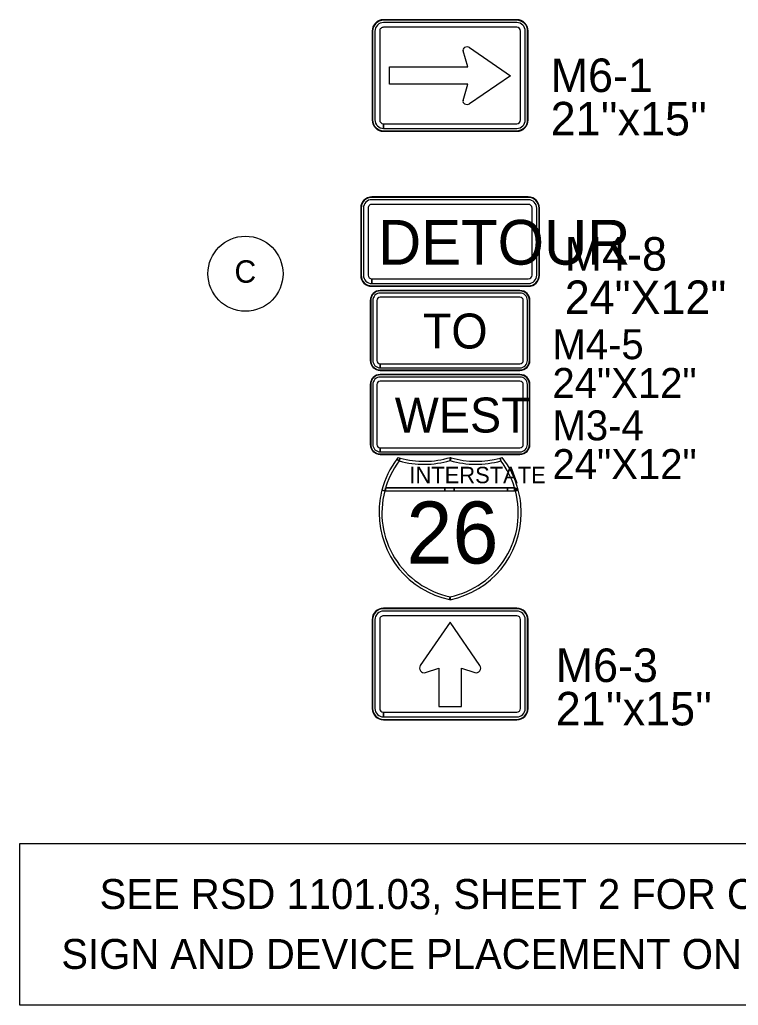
# Model space of a CAD drawing. Extents: x 886234 to 968767, y 455416 to 684046.
# Drawn here: x 931806 to 935407, y 525352 to 530289 of the extents above; entities that cross this region are included whole.
import ezdxf

# ---------------------------------------------------------------- set-up
doc = ezdxf.new("R2010")
doc.units = 0
for name, color, linetype in [('TC DEV SIGN BLACK 239', 7, 'Continuous'), ('TC DEV SIGN BLACK ZERO', 7, 'Continuous'), ('TC DEV SIGN ORANGE', 7, 'Continuous'), ('TC DEV SIGN WHITE', 7, 'Continuous'), ('TC LABEL TEXT', 7, 'Continuous')]:
    doc.layers.add(name, color=color, linetype=linetype)

msp = doc.modelspace()

# ---------------------------------------------------------------- linework, layer by layer
at = {"layer": 'TC DEV SIGN BLACK 239'}
for p, q in [((934296.9, 530274.6), (933629, 530274.6)), ((933586.4, 530232), (933586.4, 529786.8)), ((933610.1, 530232), (933610.1, 529786.8)), ((934296.9, 530251), (933629, 530251)), ((934315.8, 529786.8), (934315.8, 530232)), ((934339.5, 529786.8), (934339.5, 530232)), ((934051.6, 530052.1), (934028.4, 530132.7)), ((934060.5, 530149.9), (934265.8, 530008.5)), ((933659.7, 529966.3), (933659.7, 530052.1)), ((933659.7, 530052.1), (934051.6, 530052.1)), ((934265.8, 530008.5), (934060.5, 529867.1)), ((934051.5, 529966.3), (933659.7, 529966.3)), ((934028.4, 529884.3), (934051.5, 529966.3)), ((933629, 529744.2), (933629, 529767.8)), ((933629.2, 529767.8), (934296.9, 529767.8)), ((933629.2, 529767.8), (933629.2, 529744.2)), ((933629.2, 529744.2), (934296.9, 529744.2)), ((934313, 528499.1), (933612.9, 528499.1)), ((933575.4, 528461.6), (933575.4, 528161.6)), ((933596.2, 528461.6), (933596.2, 528161.6)), ((934313, 528478.3), (933612.9, 528478.3)), ((934329.7, 528161.6), (934329.7, 528461.6)), ((934350.5, 528161.6), (934350.5, 528461.6)), ((933612.9, 528124.1), (933612.9, 528144.9)), ((933613.1, 528144.9), (934313, 528144.9)), ((933613.1, 528144.9), (933613.1, 528124.1)), ((933613.1, 528124.1), (934313, 528124.1)), ((934296.9, 527326.5), (933629, 527326.5)), ((933586.4, 527283.9), (933586.4, 526838.7)), ((933610.1, 527283.9), (933610.1, 526838.7)), ((934296.9, 527302.9), (933629, 527302.9)), ((934315.8, 526838.7), (934315.8, 527283.9)), ((934339.5, 526838.7), (934339.5, 527283.9)), ((933629, 526796.1), (933629, 526819.7)), ((933629.2, 526819.7), (934296.9, 526819.7)), ((933629.2, 526819.7), (933629.2, 526796.1)), ((933629.2, 526796.1), (934296.9, 526796.1))]:
    msp.add_line(p, q, dxfattribs=at)
for points in [[(934112.4, 527053.3), (933962.9, 527271.1), (933813.6, 527053.3)], [(934112.4, 527053.3), (933962.9, 527271.1), (933813.6, 527053.3)], [(934112.4, 527053.3), (933962.9, 527271.1), (933813.6, 527053.3)], [(933839.2, 527018.8), (933906.2, 527040), (933906.2, 526849.1), (934019.7, 526849.1)], [(933839.2, 527018.8), (933906.2, 527040), (933906.2, 526849.1), (934019.7, 526849.1)], [(933839.2, 527018.8), (933906.2, 527040), (933906.2, 526849.1), (934019.7, 526849.1)], [(934019.7, 526849.1), (934019.7, 527040), (934086.8, 527018.8)], [(934019.7, 526849.1), (934019.7, 527040), (934086.8, 527018.8)], [(934019.7, 526849.1), (934019.7, 527040), (934086.8, 527018.8)]]:
    msp.add_lwpolyline(points, dxfattribs=at)
for centre, start, end in [((933832.3, 527040.4), 145.5508, 287.601), ((933832.3, 527040.4), 145.5508, 287.601), ((933832.3, 527040.4), 145.5508, 287.601), ((934093.6, 527040.4), 252.399, 34.4492), ((934093.6, 527040.4), 252.399, 34.4492), ((934093.6, 527040.4), 252.399, 34.4492)]:
    msp.add_arc(centre, 22.7, start, end, dxfattribs=at)
for centre, major_axis, ratio, start_param, end_param in [((933629, 530232), (42.6, 0), 0.999865, 1.570796, 3.141593), ((934296.9, 530232), (42.6, 0), 0.999865, 0, 1.570796), ((933629, 530232), (18.9, 0), 0.999865, 1.570796, 3.141593), ((934296.9, 530232), (18.9, 0), 0.999865, 0, 1.570796), ((934048.5, 530137.3), (21.1, 0), 0.720018, 0.96961, 3.452569), ((934048.5, 529879.6), (21.1, 0), 0.720018, 2.830617, 5.313577), ((933629, 529786.8), (42.6, 0), 0.999865, 3.141593, 4.712389), ((933629, 529786.8), (18.9, 0), 0.999865, 3.141593, 4.712389), ((934296.9, 529786.8), (42.6, 0), 0.999865, 4.712389, 6.283185), ((934296.9, 529786.8), (18.9, 0), 0.999865, 4.712389, 6.283185), ((933612.9, 528461.6), (37.5, 0), 0.999865, 1.570796, 3.141593), ((934313, 528461.6), (37.5, 0), 0.999865, 0, 1.570796), ((933612.9, 528461.6), (16.7, 0), 0.999865, 1.570796, 3.141593), ((934313, 528461.6), (16.7, 0), 0.999865, 0, 1.570796), ((933612.9, 528161.6), (37.5, 0), 0.999865, 3.141593, 4.712389), ((933612.9, 528161.6), (16.7, 0), 0.999865, 3.141593, 4.712389), ((934313, 528161.6), (37.5, 0), 0.999865, 4.712389, 6.283185), ((934313, 528161.6), (16.7, 0), 0.999865, 4.712389, 6.283185), ((933629, 527283.9), (42.6, 0), 0.999865, 1.570796, 3.141593), ((934296.9, 527283.9), (42.6, 0), 0.999865, 0, 1.570796), ((933629, 527283.9), (18.9, 0), 0.999865, 1.570796, 3.141593), ((934296.9, 527283.9), (18.9, 0), 0.999865, 0, 1.570796), ((933629, 526838.7), (42.6, 0), 0.999865, 3.141593, 4.712389), ((933629, 526838.7), (18.9, 0), 0.999865, 3.141593, 4.712389), ((934296.9, 526838.7), (42.6, 0), 0.999865, 4.712389, 6.283185), ((934296.9, 526838.7), (18.9, 0), 0.999865, 4.712389, 6.283185)]:
    msp.add_ellipse(centre, major_axis=major_axis, ratio=ratio, start_param=start_param, end_param=end_param, dxfattribs=at)
at = {"layer": 'TC DEV SIGN BLACK ZERO'}
for p, q in [((934296.9, 530288.8), (933629, 530288.8)), ((933629, 530286.5), (933629, 530286.5)), ((934296.9, 530286.5), (933629, 530286.5)), ((934296.9, 530286.5), (934296.9, 530286.5)), ((933572.2, 530232), (933572.2, 529786.8)), ((933574.6, 530232), (933574.6, 529786.8)), ((933574.6, 530232), (933574.6, 530232)), ((934351.3, 530232), (934351.3, 530232)), ((934351.3, 529786.8), (934351.3, 530232)), ((934353.7, 529786.8), (934353.7, 530232)), ((933574.6, 529786.8), (933574.6, 529786.8)), ((934351.3, 529786.8), (934351.3, 529786.8)), ((933629, 529730), (933629, 529732.4)), ((933629, 529732.4), (933629, 529732.3)), ((933629.1, 529732.4), (934296.9, 529732.4)), ((933629.1, 529732.4), (933629.1, 529730)), ((933629.1, 529730), (934296.9, 529730)), ((934296.9, 529732.3), (934296.9, 529732.4)), ((934355, 529401.3), (933570.9, 529401.3)), ((933570.9, 529398.9), (933570.9, 529399)), ((934355, 529398.9), (933570.9, 529399)), ((934355, 529387.3), (933570.9, 529387.3)), ((934355, 529398.9), (934355, 529398.9)), ((933514.8, 529345.3), (933514.8, 529009.3)), ((933517.2, 529345.3), (933517.2, 529009.3)), ((933517.2, 529345.3), (933517.2, 529345.3)), ((933528.8, 529345.3), (933528.8, 529009.3)), ((933552.2, 529345.3), (933552.2, 529009.3)), ((934355, 529363.9), (933570.9, 529363.9)), ((934373.6, 529009.3), (934373.6, 529345.3)), ((934397, 529009.3), (934397, 529345.3)), ((934408.6, 529345.3), (934408.7, 529345.3)), ((934408.7, 529009.3), (934408.7, 529345.3)), ((934411, 529009.3), (934411, 529345.3)), ((933517.2, 529009.3), (933517.2, 529009.3)), ((933570.9, 528967.3), (933570.9, 528990.6)), ((933571.1, 528990.6), (934355, 528990.6)), ((933571.1, 528990.6), (933571.1, 528967.3)), ((934408.7, 529009.3), (934408.6, 529009.3)), ((933570.9, 528953.3), (933570.9, 528955.6)), ((933570.9, 528955.6), (933570.9, 528955.6)), ((933570.9, 528955.6), (934355, 528955.6)), ((933570.9, 528955.6), (933570.9, 528953.3)), ((933570.9, 528953.3), (934355, 528953.3)), ((933571.1, 528967.3), (934355, 528967.3)), ((934355, 528955.6), (934355, 528955.6)), ((934313, 528932.4), (933612.9, 528932.4)), ((933612.9, 528930.4), (933612.9, 528930.4)), ((934313, 528930.3), (933612.9, 528930.4)), ((934313, 528919.9), (933612.9, 528919.9)), ((934313, 528899.1), (933612.9, 528899.1)), ((934313, 528930.3), (934313, 528930.4)), ((933562.9, 528882.4), (933562.9, 528582.4)), ((933564.9, 528882.4), (933564.9, 528582.4)), ((933564.9, 528882.4), (933565, 528882.4)), ((933575.4, 528882.4), (933575.4, 528582.4)), ((933596.2, 528882.4), (933596.2, 528582.4)), ((934329.6, 528582.4), (934329.6, 528882.4)), ((934350.5, 528582.4), (934350.5, 528882.4)), ((934360.9, 528882.4), (934360.9, 528882.4)), ((934360.9, 528582.4), (934360.9, 528882.4)), ((934363, 528582.4), (934363, 528882.4)), ((933565, 528582.4), (933564.9, 528582.4)), ((933612.9, 528544.9), (933612.9, 528565.8)), ((933613.1, 528565.8), (934313, 528565.8)), ((933613.1, 528565.8), (933613.1, 528544.9)), ((933613.1, 528544.9), (934313, 528544.9)), ((934360.9, 528582.4), (934360.9, 528582.4)), ((933612.9, 528532.4), (933612.9, 528534.5)), ((933612.9, 528534.5), (933612.9, 528534.5)), ((933612.9, 528534.5), (934313, 528534.5)), ((933612.9, 528534.5), (933612.9, 528532.4)), ((933612.9, 528532.4), (934313, 528532.4)), ((934313, 528511.6), (933612.9, 528511.6)), ((933612.9, 528509.5), (933612.9, 528509.5)), ((934313, 528509.5), (933612.9, 528509.5)), ((934313, 528534.5), (934313, 528534.5)), ((934313, 528509.5), (934313, 528509.5)), ((933562.9, 528461.6), (933562.9, 528161.6)), ((933565, 528461.6), (933565, 528161.6)), ((933565, 528461.6), (933565, 528461.6)), ((934360.9, 528461.6), (934360.9, 528461.6)), ((934360.9, 528161.6), (934360.9, 528461.6)), ((934363, 528161.6), (934363, 528461.6)), ((933565, 528161.6), (933565, 528161.6)), ((934360.9, 528161.6), (934360.9, 528161.6)), ((933612.9, 528111.6), (933612.9, 528113.7)), ((933612.9, 528113.7), (933612.9, 528113.7)), ((933612.9, 528113.7), (934313, 528113.7)), ((933612.9, 528113.7), (933612.9, 528111.6)), ((933612.9, 528111.6), (934313, 528111.6)), ((934313, 528113.7), (934313, 528113.7)), ((933963.3, 528081.7), (933963, 528096.1)), ((934213.7, 528093.3), (934217.7, 528079)), ((933935.8, 527944.2), (933639.9, 527944.2)), ((933639.9, 527929.3), (933935.8, 527929.3)), ((933982.7, 527944.2), (933935.8, 527944.2)), ((933935.8, 527929.3), (933982.7, 527929.3)), ((934251.1, 527944.2), (933982.7, 527944.2)), ((933982.7, 527929.3), (934251.1, 527929.3)), ((934286.1, 527944.2), (934251.1, 527944.2)), ((934251.1, 527929.3), (934286.1, 527929.3)), ((933606.7, 527822.1), (933606.7, 527817.7)), ((934319.2, 527817.6), (934319.2, 527822.3)), ((934296.9, 527340.7), (933629, 527340.7)), ((933629, 527338.4), (933629, 527338.4)), ((934296.9, 527338.4), (933629, 527338.4)), ((934296.9, 527338.4), (934296.9, 527338.4)), ((933572.2, 527283.9), (933572.2, 526838.7)), ((933574.6, 527283.9), (933574.6, 526838.7)), ((933574.6, 527283.9), (933574.6, 527283.9)), ((934351.3, 527283.9), (934351.3, 527283.9)), ((934351.3, 526838.7), (934351.3, 527283.9)), ((934353.7, 526838.7), (934353.7, 527283.9)), ((933574.6, 526838.7), (933574.6, 526838.7)), ((934351.3, 526838.7), (934351.3, 526838.7)), ((933629, 526781.9), (933629, 526784.3)), ((933629, 526784.3), (933629, 526784.2)), ((933629.1, 526784.3), (934296.9, 526784.3)), ((933629.1, 526784.3), (933629.1, 526781.9)), ((933629.1, 526781.9), (934296.9, 526781.9)), ((934296.9, 526784.2), (934296.9, 526784.3))]:
    msp.add_line(p, q, dxfattribs=at)
for points in [[(933708.2, 528079), (933696.4, 528088)], [(933712.3, 528093.3), (933708.2, 528079)], [(933963, 528080.6), (933963.3, 528081.7)], [(933967.5, 528094.7), (933963.4, 528080.6)], [(934217.7, 528079), (934213.7, 528093.3)], [(934223.2, 528096.1), (934223.2, 528096.1), (934223.2, 528096.1)], [(933635.7, 527929.3), (933621.3, 527933.1)], [(933621.3, 527933.1), (933635.7, 527929.3)], [(933639.9, 527944.2), (933639.9, 527929.3)], [(933935.8, 527929.3), (933935.8, 527944.2)], [(933935.8, 527944.2), (933935.8, 527929.3)], [(933982.7, 527944.2), (933982.7, 527929.3)], [(933982.7, 527929.3), (933982.7, 527944.2)], [(934251.1, 527929.3), (934251.1, 527944.2)], [(934251.1, 527944.2), (934251.1, 527929.3)], [(934286.1, 527944.2), (934304.6, 527933.1)], [(934286.1, 527929.3), (934286.1, 527944.2)], [(934304.6, 527933.1), (934290.2, 527929.3)], [(933959.9, 527384.2), (933963, 527398.8)], [(933963, 527398.8), (933963, 527383.6)]]:
    msp.add_lwpolyline(points, dxfattribs=at)
for centre, radius, start, end in [((934052, 527819.9), 445.3, 142.9968, 165.2769), ((934052, 527819.9), 430.5, 142.9968, 165.2769), ((933832.8, 528522), 460.2, 254.2907, 286.4259), ((933832.8, 528522), 445.3, 254.2907, 286.9893), ((934093.3, 528521.3), 459.4, 253.5731, 285.7093), ((934093.1, 528522), 445.3, 253.6206, 285.7093), ((934093.1, 528522), 445.3, 285.7093, 286.9901), ((933873.9, 527819.9), 430.5, 16.7759, 37.0032), ((933873.9, 527819.9), 445.3, 14.7231, 38.3291), ((934052, 527819.9), 445.3, 165.2769, 179.7177), ((934049.9, 527818.6), 428.8, 165.0438, 258.3001), ((933876, 527818.6), 428.8, 281.7196, 14.964), ((933873.9, 527819.9), 445.3, 0.2997, 14.7231), ((934052, 527819.9), 445.3, 180.2823, 258.0591), ((933873.9, 527819.9), 445.3, 281.537, 359.7003), ((933873.9, 527819.9), 430.5, 281.9405, 281.9604)]:
    msp.add_arc(centre, radius, start, end, dxfattribs=at)
for centre, major_axis, start_param, end_param in [((933629, 530232), (56.8, 0), 1.570796, 3.141593), ((933629, 530232), (54.4, 0), 1.570796, 3.141593), ((934296.9, 530232), (56.8, 0), 0, 1.570796), ((934296.9, 530232), (54.4, 0), 0, 1.570796), ((933629, 529786.8), (56.8, 0), 3.141593, 4.712389), ((933629, 529786.8), (54.4, 0), 3.141593, 4.712389), ((934296.9, 529786.8), (56.8, 0), 4.712389, 6.283185), ((934296.9, 529786.8), (54.4, 0), 4.712389, 6.283185), ((933570.9, 529345.3), (56, 0), 1.570796, 3.141593), ((933570.9, 529345.3), (53.7, 0), 1.570796, 3.141593), ((933570.9, 529345.3), (42, 0), 1.570796, 3.141593), ((934355, 529345.3), (56, 0), 0, 1.570796), ((934355, 529345.3), (53.7, 0), 0, 1.570796), ((934355, 529345.3), (42, 0), 0, 1.570796), ((933570.9, 529345.3), (18.7, 0), 1.570796, 3.141593), ((934355, 529345.3), (18.7, 0), 0, 1.570796), ((933570.9, 529009.3), (56, 0), 3.141593, 4.712389), ((933570.9, 529009.3), (53.7, 0), 3.141593, 4.712389), ((933570.9, 529009.3), (42, 0), 3.141593, 4.712389), ((933570.9, 529009.3), (18.7, 0), 3.141593, 4.712389), ((934355, 529009.3), (42, 0), 4.712389, 6.283185), ((934355, 529009.3), (18.7, 0), 4.712389, 6.283185), ((934355, 529009.3), (56, 0), 4.712389, 6.283185), ((934355, 529009.3), (53.7, 0), 4.712389, 6.283185), ((933612.9, 528882.4), (50, 0), 1.570796, 3.141593), ((933612.9, 528882.4), (47.9, 0), 1.570796, 3.141593), ((933612.9, 528882.4), (37.5, 0), 1.570796, 3.141593), ((933612.9, 528882.4), (16.7, 0), 1.570796, 3.141593), ((934313, 528882.4), (50, 0), 0, 1.570796), ((934313, 528882.4), (47.9, 0), 0, 1.570796), ((934313, 528882.4), (37.5, 0), 0, 1.570796), ((934313, 528882.4), (16.7, 0), 0, 1.570796), ((933612.9, 528582.4), (50, 0), 3.141593, 4.712389), ((933612.9, 528582.4), (47.9, 0), 3.141593, 4.712389), ((933612.9, 528582.4), (37.5, 0), 3.141593, 4.712389), ((933612.9, 528582.4), (16.7, 0), 3.141593, 4.712389), ((934313, 528582.4), (37.5, 0), 4.712389, 6.283185), ((934313, 528582.4), (16.7, 0), 4.712389, 6.283185), ((934313, 528582.4), (50, 0), 4.712389, 6.283185), ((934313, 528582.4), (47.9, 0), 4.712389, 6.283185), ((933612.9, 528461.6), (50, 0), 1.570796, 3.141593), ((933612.9, 528461.6), (47.9, 0), 1.570796, 3.141593), ((934313, 528461.6), (50, 0), 0, 1.570796), ((934313, 528461.6), (47.9, 0), 0, 1.570796), ((933612.9, 528161.6), (50, 0), 3.141593, 4.712389), ((933612.9, 528161.6), (47.9, 0), 3.141593, 4.712389), ((934313, 528161.6), (50, 0), 4.712389, 6.283185), ((934313, 528161.6), (47.9, 0), 4.712389, 6.283185), ((933629, 527283.9), (56.8, 0), 1.570796, 3.141593), ((933629, 527283.9), (54.4, 0), 1.570796, 3.141593), ((934296.9, 527283.9), (56.8, 0), 0, 1.570796), ((934296.9, 527283.9), (54.4, 0), 0, 1.570796), ((933629, 526838.7), (56.8, 0), 3.141593, 4.712389), ((933629, 526838.7), (54.4, 0), 3.141593, 4.712389), ((934296.9, 526838.7), (56.8, 0), 4.712389, 6.283185), ((934296.9, 526838.7), (54.4, 0), 4.712389, 6.283185)]:
    msp.add_ellipse(centre, major_axis=major_axis, ratio=0.999865, start_param=start_param, end_param=end_param, dxfattribs=at)
at = {"layer": 'TC DEV SIGN ORANGE'}
for p, q in [((934355, 529401.3), (933570.9, 529401.3)), ((933514.8, 529345.3), (933514.8, 529009.3)), ((934411, 529009.3), (934411, 529345.3)), ((933570.9, 528953.3), (934355, 528953.3)), ((934313, 528932.4), (933612.9, 528932.4)), ((933562.9, 528882.4), (933562.9, 528582.4)), ((934363, 528582.4), (934363, 528882.4)), ((933612.9, 528532.4), (934313, 528532.4))]:
    msp.add_line(p, q, dxfattribs=at)
for centre, major_axis, start_param, end_param in [((933570.9, 529345.3), (56, 0), 1.570796, 3.141593), ((934355, 529345.3), (56, 0), 0, 1.570796), ((933570.9, 529009.3), (56, 0), 3.141593, 4.712389), ((934355, 529009.3), (56, 0), 4.712389, 6.283185), ((933612.9, 528882.4), (50, 0), 1.570796, 3.141593), ((934313, 528882.4), (50, 0), 0, 1.570796), ((933612.9, 528582.4), (50, 0), 3.141593, 4.712389), ((934313, 528582.4), (50, 0), 4.712389, 6.283185)]:
    msp.add_ellipse(centre, major_axis=major_axis, ratio=0.999865, start_param=start_param, end_param=end_param, dxfattribs=at)
at = {"layer": 'TC DEV SIGN WHITE'}
for p, q in [((934296.9, 530288.8), (933629, 530288.8)), ((933572.2, 530232), (933572.2, 529786.8)), ((934353.7, 529786.8), (934353.7, 530232)), ((933629, 529730), (934296.9, 529730)), ((934313, 528511.6), (933612.9, 528511.6)), ((933562.9, 528461.6), (933562.9, 528161.6)), ((934363, 528161.6), (934363, 528461.6)), ((933612.9, 528111.6), (934313, 528111.6)), ((933708.2, 528079), (933712.3, 528093.3)), ((933963.4, 528080.6), (933963, 528096.1)), ((933635.7, 527929.3), (934290.2, 527929.3)), ((933635.7, 527929.3), (933639.9, 527929.3)), ((933639.9, 527944.2), (934286.1, 527944.2)), ((934304.6, 527933.1), (934286.1, 527944.2)), ((934289.9, 527930.4), (934286.1, 527929.3)), ((934286.1, 527929.3), (934290.2, 527929.3)), ((933963, 527383.6), (933963, 527398.8)), ((934296.9, 527340.7), (933629, 527340.7)), ((933572.2, 527283.9), (933572.2, 526838.7)), ((934353.7, 526838.7), (934353.7, 527283.9)), ((933629, 526781.9), (934296.9, 526781.9))]:
    msp.add_line(p, q, dxfattribs=at)
for points in [[(933696.4, 528088), (933708.2, 528079)], [(933702.7, 528096.1), (933702.7, 528096.1), (933702.7, 528096.1)], [(933963.3, 528096), (933963.3, 528081.7), (933967.5, 528094.7)], [(933639.9, 527929.3), (933639.9, 527944.2)], [(934286.1, 527944.2), (934286.1, 527929.3), (934289.9, 527930.4), (934286.1, 527944.2)], [(934290.2, 527929.3), (934289.9, 527930.4)], [(934290.2, 527929.3), (934304.6, 527933.1)], [(933963, 527398.8), (933959.9, 527384.2), (933962.9, 527383.6)]]:
    msp.add_lwpolyline(points, dxfattribs=at)
for centre, radius, start, end in [((934052, 527819.9), 445.3, 141.6709, 142.9968), ((933832.8, 528522), 445.3, 253.0099, 254.2907), ((934093.1, 528522), 445.3, 253.0588, 253.6206), ((934052, 527819.9), 430.5, 163.2241, 165.2769), ((933873.9, 527819.9), 430.5, 14.7231, 16.7759), ((934052, 527819.9), 445.3, 258.458, 258.463), ((933873.9, 527819.9), 445.3, 281.5369590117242, 281.53700435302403)]:
    msp.add_arc(centre, radius, start, end, dxfattribs=at)
for centre, major_axis, start_param, end_param in [((933629, 530232), (56.8, 0), 1.570796, 3.141593), ((934296.9, 530232), (56.8, 0), 0, 1.570796), ((933629, 529786.8), (56.8, 0), 3.141593, 4.712389), ((934296.9, 529786.8), (56.8, 0), 4.712389, 6.283185), ((933612.9, 528461.6), (50, 0), 1.570796, 3.141593), ((934313, 528461.6), (50, 0), 0, 1.570796), ((933612.9, 528161.6), (50, 0), 3.141593, 4.712389), ((934313, 528161.6), (50, 0), 4.712389, 6.283185), ((933629, 527283.9), (56.8, 0), 1.570796, 3.141593), ((934296.9, 527283.9), (56.8, 0), 0, 1.570796), ((933629, 526838.7), (56.8, 0), 3.141593, 4.712389), ((934296.9, 526838.7), (56.8, 0), 4.712389, 6.283185)]:
    msp.add_ellipse(centre, major_axis=major_axis, ratio=0.999865, start_param=start_param, end_param=end_param, dxfattribs=at)
at = {"layer": 'TC LABEL TEXT'}
msp.add_lwpolyline([(931806, 526162), (937004.8, 526162), (937004.8, 525352), (931806, 525352)], close=True, dxfattribs=at)
msp.add_circle((932937.5, 529016.6), 188.1, dxfattribs=at)

# ---------------------------------------------------------------- texts
at = {"layer": 'TC DEV SIGN BLACK 239'}
msp.add_text('WEST', height=175, rotation=360, dxfattribs=at).set_placement((933685.6, 528221.1))
at = {"layer": 'TC DEV SIGN BLACK ZERO'}
for s, height, p in [('M6-1', 168, (934467.1, 529926.5)), ("21''x15''", 168, (934467.1, 529709.2)), ('M4-8', 168, (934537.7, 529031.7)), ('24"X12"', 168, (934537.7, 528814.5)), ('TO', 175, (933826.1, 528641.9)), ('M4-5', 150, (934475.9, 528588.4)), ('24"X12"', 150, (934475.9, 528394.4)), ('M3-4', 150, (934476.2, 528181.7)), ('24"X12"', 150, (934476.2, 527987.7)), ('INTERSTATE', 82.13, (933758.9, 527967.2)), ('26', 310.26, (933744, 527564.9)), ('M6-3', 168, (934492.5, 526971.2)), ("21''x15''", 168, (934492.5, 526753.9))]:
    msp.add_text(s, height=height, rotation=360, dxfattribs=at).set_placement(p)
msp.add_text('DETOUR', height=224, dxfattribs=at).set_placement((933601.9, 529061.9))
at = {"layer": 'TC LABEL TEXT'}
for s, height, p in [('C', 112.5, (932882.4, 528971.2)), ('SEE RSD 1101.03, SHEET 2 FOR CLOSURE ', 150, (932206.5, 525834.2)), ('SIGN AND DEVICE PLACEMENT ON AMBOY RD', 150, (932014.6, 525534.2))]:
    msp.add_text(s, height=height, dxfattribs=at).set_placement(p)

doc.saveas('drawing.dxf')
